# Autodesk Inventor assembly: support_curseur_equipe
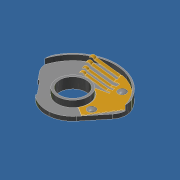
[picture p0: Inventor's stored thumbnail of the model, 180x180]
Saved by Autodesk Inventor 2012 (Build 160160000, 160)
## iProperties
Created: 2011-10
Part Number: support_curseur_equipe
Document SubType Name: Assembly
Designer: didierf
Author: didierf
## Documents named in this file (4)
- D:\Formulaire\Sujet CIM 2012\Modélisation_7970_shimano\support_curseur_equipe.iam
- D:\Formulaire\Sujet CIM 2012\Modélisation_7970_shimano\support_curseur.ipt
- support curseur.ipt
- D:\Formulaire\Sujet CIM 2012\Modélisation_7970_shimano\curseur.ipt
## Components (2 placed, 2 different names)
1. support curseur:1 — Placage:1, Placage:2, Placage:3
2. curseur:1 — Placage:1, Placage:2, Placage:3
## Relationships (3: Mate 3)
- Placage:1 [Mate]: support curseur:1 ↔ curseur:1
- Placage:2 [Mate]: support curseur:1 ↔ curseur:1
- Placage:3 [Mate]: support curseur:1 ↔ curseur:1
